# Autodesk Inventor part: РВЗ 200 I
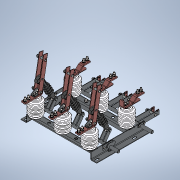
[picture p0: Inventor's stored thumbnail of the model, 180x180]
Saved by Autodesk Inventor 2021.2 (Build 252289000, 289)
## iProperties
Created: 1900-01
Part Number: РВЗ 200 I
Material: Типовые
Description: STEP AP242
Document SubType Name: Modeling
Designer: pc
Density: 1 g/cm^3
Appearance: По умолчанию
Company: UNSPECIFIED
Title: ÐÂÇ 200 I
Author: UNSPECIFIED
Revision Number: ANYUNSPECIFIED
Sending System: C3D Toolkit
Preprocessor: C3D Converter
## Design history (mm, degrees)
feature "БазТело1"
feature "БазТело2"
feature "БазТело3"
feature "БазТело4"
feature "Составной1"
node "Твердое тело1"
node "Твердое тело2"
node "Твердое тело3"
node "Твердое тело4"
body "SRF1"
